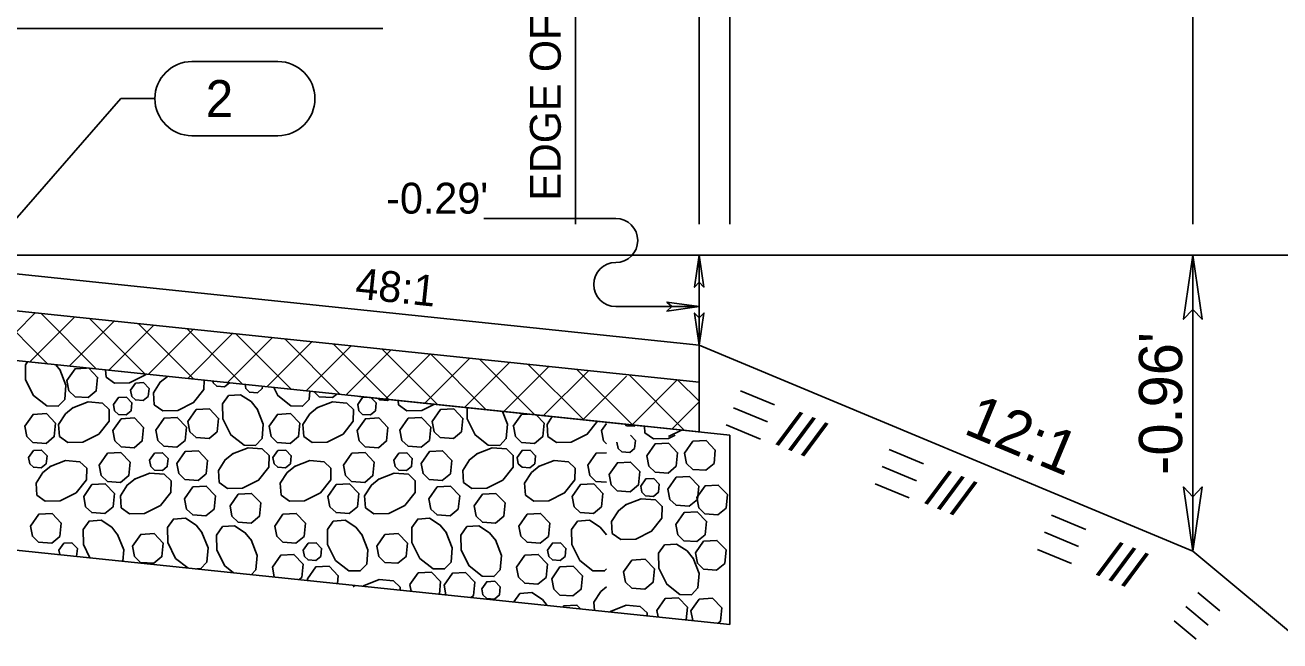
# Model space of a CAD drawing. Extents: x 6561 to 6787, y 19927 to 20919.
# Drawn here: x 6704.14 to 6724.47, y 20747.4 to 20757.37 of the extents above; entities that cross this region are included whole.
import ezdxf

# ---------------------------------------------------------------- set-up
doc = ezdxf.new("R2010")
doc.units = 0
for name, color, linetype in [('Level 1', 7, 'Continuous'), ('Level 3', 7, 'Continuous'), ('Level 5', 7, 'Continuous'), ('Level 7', 7, 'Continuous'), ('Level 8', 7, 'Continuous')]:
    doc.layers.add(name, color=color, linetype=linetype)

msp = doc.modelspace()

# ---------------------------------------------------------------- linework, layer by layer
at = {"layer": 'Level 1'}
for p, q in [((6723.057, 20767.65), (6723.057, 20754.15)), ((6713.057, 20764.65), (6713.057, 20754.15)), ((6715.057, 20764.65), (6715.057, 20754.15)), ((6715.557, 20762.65), (6715.557, 20754.15)), ((6713.708, 20754.242), (6711.572, 20754.242)), ((6779.047, 20753.65), (6628.473, 20753.65)), ((6715.057, 20753.65), (6715.057, 20752.192)), ((6723.057, 20748.858), (6723.057, 20753.65)), ((6713.708, 20752.817), (6715.057, 20752.817))]:
    msp.add_line(p, q, dxfattribs=at)
for points in [[(6715.057, 20753.65), (6714.985, 20753.13), (6715.059, 20753.211), (6715.135, 20753.131)], [(6723.057, 20753.65), (6722.907, 20752.611), (6723.057, 20752.771), (6723.207, 20752.611)], [(6715.057, 20752.817), (6714.537, 20752.889), (6714.618, 20752.815), (6714.538, 20752.739)], [(6715.057, 20752.192), (6714.985, 20752.711), (6715.059, 20752.631), (6715.135, 20752.711)], [(6723.057, 20748.858), (6723.207, 20749.897), (6723.057, 20749.737), (6722.907, 20749.897)]]:
    msp.add_lwpolyline(points, close=True, dxfattribs=at)
for centre, start, end in [((6713.708, 20753.886), 270, 90), ((6713.708, 20753.173), 90, 270)]:
    msp.add_arc(centre, 0.356, start, end, dxfattribs=at)
at = {"layer": 'Level 3'}
for p, q in [((6715.057, 20751.592), (6701.057, 20753.05)), ((6704.299, 20752.712), (6703.571, 20751.984)), ((6704.506, 20751.886), (6703.608, 20752.784)), ((6704.94, 20752.645), (6704.211, 20751.917)), ((6705.295, 20751.804), (6704.398, 20752.702)), ((6705.58, 20752.579), (6704.852, 20751.85)), ((6706.085, 20751.722), (6705.187, 20752.62)), ((6706.221, 20752.512), (6705.492, 20751.784)), ((6706.874, 20751.64), (6705.976, 20752.537)), ((6706.861, 20752.445), (6706.133, 20751.717)), ((6707.663, 20751.557), (6706.766, 20752.455)), ((6707.501, 20752.379), (6706.773, 20751.65)), ((6708.142, 20752.312), (6707.413, 20751.583)), ((6708.453, 20751.475), (6707.555, 20752.373)), ((6701.057, 20752.246), (6715.057, 20750.787)), ((6708.782, 20752.245), (6708.054, 20751.517)), ((6709.242, 20751.393), (6708.344, 20752.291)), ((6709.423, 20752.178), (6708.694, 20751.45)), ((6710.031, 20751.311), (6709.134, 20752.209)), ((6710.063, 20752.112), (6709.335, 20751.383)), ((6710.821, 20751.229), (6709.923, 20752.126)), ((6710.703, 20752.045), (6709.975, 20751.317)), ((6711.344, 20751.978), (6710.615, 20751.25)), ((6711.61, 20751.146), (6710.712, 20752.044)), ((6711.984, 20751.912), (6711.256, 20751.183)), ((6712.399, 20751.064), (6711.501, 20751.962)), ((6712.625, 20751.845), (6711.896, 20751.116)), ((6713.189, 20750.982), (6712.291, 20751.88)), ((6713.265, 20751.778), (6712.537, 20751.05)), ((6713.966, 20750.912), (6713.08, 20751.797)), ((6714.821, 20750.812), (6713.923, 20751.71)), ((6713.881, 20751.687), (6713.177, 20750.983)), ((6714.703, 20751.628), (6713.975, 20750.9)), ((6715.057, 20751.283), (6714.712, 20751.627)), ((6715.057, 20750.787), (6715.057, 20751.592)), ((6715.057, 20751.275), (6714.615, 20750.833))]:
    msp.add_line(p, q, dxfattribs=at)
at = {"layer": 'Level 5'}
for p, q in [((6701.057, 20752.246), (6713.557, 20750.944)), ((6709.557, 20751.36), (6714.16, 20750.881)), ((6714.174, 20750.879), (6715.557, 20750.735)), ((6715.557, 20750.735), (6715.557, 20747.669)), ((6715.557, 20747.669), (6701.057, 20749.179))]:
    msp.add_line(p, q, dxfattribs=at)
for points in [[(6704.701, 20751.796), (6704.8, 20751.544), (6704.78, 20751.313), (6704.676, 20751.203), (6704.489, 20751.207), (6704.275, 20751.374), (6704.147, 20751.631), (6704.142, 20751.874), (6704.176, 20751.921)], [(6704.638, 20751.873), (6704.707, 20751.786)], [(6704.815, 20751.619), (6704.949, 20751.81), (6705.135, 20751.821)], [(6705.169, 20751.817), (6705.313, 20751.668), (6705.292, 20751.451), (6705.159, 20751.341), (6704.947, 20751.356), (6704.847, 20751.453), (6704.815, 20751.619)], [(6706.096, 20751.721), (6706.088, 20751.711), (6705.83, 20751.582), (6705.588, 20751.578), (6705.451, 20751.675), (6705.443, 20751.789)], [(6705.847, 20751.462), (6705.927, 20751.577), (6706.056, 20751.584), (6706.146, 20751.491), (6706.133, 20751.361), (6706.053, 20751.295), (6705.926, 20751.304), (6705.866, 20751.362), (6705.847, 20751.462)], [(6707.038, 20751.623), (6707.035, 20751.474), (6706.868, 20751.261), (6706.611, 20751.133), (6706.368, 20751.128), (6706.231, 20751.225), (6706.218, 20751.419), (6706.329, 20751.592), (6706.445, 20751.684)], [(6707.448, 20751.58), (6707.371, 20751.516), (6707.244, 20751.525), (6707.184, 20751.583), (6707.179, 20751.608)], [(6707.984, 20751.524), (6707.98, 20751.487), (6707.901, 20751.421), (6707.773, 20751.43), (6707.714, 20751.488), (6707.701, 20751.554)], [(6708.749, 20751.444), (6708.738, 20751.313), (6708.633, 20751.203), (6708.446, 20751.207), (6708.233, 20751.374), (6708.167, 20751.505)], [(6705.569, 20751.229), (6705.65, 20751.343), (6705.779, 20751.351), (6705.868, 20751.258), (6705.855, 20751.128), (6705.776, 20751.062), (6705.649, 20751.071), (6705.589, 20751.129), (6705.569, 20751.229)], [(6707.897, 20751.161), (6707.997, 20750.91), (6707.977, 20750.679), (6707.873, 20750.569), (6707.685, 20750.572), (6707.472, 20750.739), (6707.343, 20750.997), (6707.339, 20751.239), (6707.436, 20751.376), (6707.629, 20751.389), (6707.802, 20751.278), (6707.904, 20751.151)], [(6709.187, 20751.399), (6709.116, 20751.341), (6708.905, 20751.356), (6708.821, 20751.437)], [(6709.527, 20751.229), (6709.607, 20751.343), (6709.679, 20751.347)], [(6709.746, 20751.34), (6709.826, 20751.258), (6709.813, 20751.128), (6709.733, 20751.062), (6709.606, 20751.071), (6709.546, 20751.129), (6709.527, 20751.229)], [(6710.03, 20751.311), (6710.011, 20751.295), (6709.883, 20751.304), (6709.858, 20751.329)], [(6710.771, 20751.234), (6710.568, 20751.133), (6710.325, 20751.128), (6710.189, 20751.225), (6710.184, 20751.295)], [(6704.909, 20751.174), (6705.16, 20751.274), (6705.391, 20751.254), (6705.501, 20751.149), (6705.498, 20750.962), (6705.331, 20750.749), (6705.074, 20750.62), (6704.831, 20750.616), (6704.694, 20750.713), (6704.681, 20750.906), (6704.792, 20751.079), (6704.919, 20751.181)], [(6706.775, 20750.956), (6706.91, 20751.148), (6707.125, 20751.16), (6707.274, 20751.005), (6707.252, 20750.788), (6707.12, 20750.678), (6706.908, 20750.694), (6706.808, 20750.79), (6706.776, 20750.956)], [(6708.866, 20751.174), (6709.118, 20751.274), (6709.349, 20751.254), (6709.459, 20751.149), (6709.455, 20750.962), (6709.289, 20750.749), (6709.031, 20750.62), (6708.788, 20750.616), (6708.652, 20750.713), (6708.639, 20750.906), (6708.75, 20751.079), (6708.877, 20751.181)], [(6710.733, 20750.956), (6710.867, 20751.148), (6711.082, 20751.16), (6711.231, 20751.005), (6711.21, 20750.788), (6711.077, 20750.678), (6710.865, 20750.694), (6710.765, 20750.79), (6710.733, 20750.956)], [(6711.871, 20751.119), (6711.954, 20750.91), (6711.934, 20750.679), (6711.83, 20750.569), (6711.643, 20750.572), (6711.429, 20750.739), (6711.301, 20750.997), (6711.298, 20751.179)], [(6704.134, 20750.879), (6704.268, 20751.071), (6704.483, 20751.083), (6704.632, 20750.928), (6704.61, 20750.711), (6704.478, 20750.601), (6704.266, 20750.616), (6704.166, 20750.713), (6704.134, 20750.879)], [(6705.56, 20750.808), (6705.695, 20751), (6705.909, 20751.012), (6706.059, 20750.857), (6706.037, 20750.64), (6705.904, 20750.53), (6705.693, 20750.545), (6705.593, 20750.642), (6705.56, 20750.808)], [(6706.254, 20750.816), (6706.389, 20751.007), (6706.603, 20751.02), (6706.752, 20750.865), (6706.731, 20750.648), (6706.598, 20750.538), (6706.386, 20750.553), (6706.287, 20750.65), (6706.254, 20750.816)], [(6708.091, 20750.879), (6708.225, 20751.071), (6708.44, 20751.083), (6708.589, 20750.928), (6708.568, 20750.711), (6708.435, 20750.601), (6708.223, 20750.616), (6708.123, 20750.713), (6708.091, 20750.879)], [(6709.518, 20750.808), (6709.652, 20751), (6709.867, 20751.012), (6710.016, 20750.857), (6709.995, 20750.64), (6709.862, 20750.53), (6709.65, 20750.545), (6709.55, 20750.642), (6709.518, 20750.808)], [(6710.211, 20750.816), (6710.346, 20751.007), (6710.561, 20751.02), (6710.71, 20750.865), (6710.688, 20750.648), (6710.556, 20750.538), (6710.344, 20750.553), (6710.244, 20750.65), (6710.212, 20750.816)], [(6712.048, 20750.879), (6712.183, 20751.071), (6712.283, 20751.076)], [(6712.417, 20751.062), (6712.547, 20750.928), (6712.525, 20750.711), (6712.393, 20750.601), (6712.181, 20750.616), (6712.081, 20750.713), (6712.049, 20750.879)], [(6713.41, 20750.959), (6713.246, 20750.749), (6712.988, 20750.62), (6712.746, 20750.616), (6712.609, 20750.713), (6712.596, 20750.906), (6712.679, 20751.035)], [(6713.475, 20750.808), (6713.557, 20750.925)], [(6714.03, 20750.894), (6714.011, 20750.878), (6713.883, 20750.887), (6713.858, 20750.912)], [(6713.557, 20750.594), (6713.508, 20750.642), (6713.475, 20750.808)], [(6713.947, 20750.732), (6714.026, 20750.649), (6714.013, 20750.519), (6713.934, 20750.453), (6713.807, 20750.462), (6713.747, 20750.52), (6713.727, 20750.62)], [(6714.669, 20750.732), (6714.561, 20750.678), (6714.318, 20750.674), (6714.181, 20750.771), (6714.174, 20750.879)], [(6714.771, 20750.817), (6714.564, 20750.714)], [(6704.195, 20750.371), (6704.275, 20750.486), (6704.404, 20750.493), (6704.494, 20750.4), (6704.481, 20750.27), (6704.401, 20750.204), (6704.274, 20750.213), (6704.214, 20750.271), (6704.195, 20750.371)], [(6706.596, 20750.277), (6706.731, 20750.469), (6706.945, 20750.481), (6707.095, 20750.326), (6707.073, 20750.109), (6706.94, 20749.999), (6706.728, 20750.014), (6706.629, 20750.111), (6706.596, 20750.277)], [(6707.499, 20750.43), (6707.75, 20750.53), (6707.981, 20750.51), (6708.091, 20750.406), (6708.087, 20750.218), (6707.921, 20750.005), (6707.663, 20749.876), (6707.42, 20749.872), (6707.284, 20749.969), (6707.271, 20750.162), (6707.382, 20750.335), (6707.509, 20750.437)], [(6708.152, 20750.371), (6708.233, 20750.486), (6708.362, 20750.493), (6708.451, 20750.4), (6708.438, 20750.27), (6708.359, 20750.204), (6708.232, 20750.213), (6708.172, 20750.271), (6708.152, 20750.371)], [(6710.554, 20750.277), (6710.688, 20750.469), (6710.903, 20750.481), (6711.052, 20750.326), (6711.03, 20750.109), (6710.898, 20749.999), (6710.686, 20750.014), (6710.586, 20750.111), (6710.554, 20750.277)], [(6711.456, 20750.43), (6711.707, 20750.53), (6711.939, 20750.51), (6712.048, 20750.406), (6712.045, 20750.218), (6711.878, 20750.005), (6711.621, 20749.876), (6711.378, 20749.872), (6711.241, 20749.969), (6711.228, 20750.162), (6711.339, 20750.335), (6711.466, 20750.437)], [(6712.11, 20750.371), (6712.19, 20750.486), (6712.319, 20750.493), (6712.409, 20750.4), (6712.396, 20750.27), (6712.316, 20750.204), (6712.189, 20750.213), (6712.129, 20750.271), (6712.11, 20750.371)], [(6714.211, 20750.4), (6714.346, 20750.591), (6714.561, 20750.603), (6714.71, 20750.448), (6714.688, 20750.232), (6714.556, 20750.121), (6714.344, 20750.137), (6714.244, 20750.233), (6714.212, 20750.4)], [(6714.823, 20750.443), (6714.958, 20750.635), (6715.172, 20750.647), (6715.321, 20750.492), (6715.3, 20750.275), (6715.167, 20750.165), (6714.955, 20750.18), (6714.856, 20750.277), (6714.823, 20750.443)], [(6704.543, 20750.224), (6704.795, 20750.323), (6705.026, 20750.304), (6705.136, 20750.199), (6705.132, 20750.012), (6704.965, 20749.799), (6704.708, 20749.67), (6704.465, 20749.666), (6704.328, 20749.763), (6704.316, 20749.956), (6704.426, 20750.129), (6704.553, 20750.23)], [(6705.34, 20750.248), (6705.474, 20750.44), (6705.689, 20750.452), (6705.838, 20750.297), (6705.817, 20750.08), (6705.684, 20749.97), (6705.472, 20749.985), (6705.372, 20750.082), (6705.34, 20750.248)], [(6706.156, 20750.327), (6706.236, 20750.442), (6706.365, 20750.449), (6706.455, 20750.356), (6706.442, 20750.226), (6706.362, 20750.16), (6706.235, 20750.169), (6706.175, 20750.227), (6706.156, 20750.327)], [(6708.501, 20750.224), (6708.752, 20750.323), (6708.983, 20750.304), (6709.093, 20750.199), (6709.09, 20750.012), (6708.923, 20749.799), (6708.665, 20749.67), (6708.423, 20749.666), (6708.286, 20749.763), (6708.273, 20749.956), (6708.384, 20750.129), (6708.511, 20750.23)], [(6709.297, 20750.248), (6709.432, 20750.44), (6709.646, 20750.452), (6709.796, 20750.297), (6709.774, 20750.08), (6709.641, 20749.97), (6709.429, 20749.985), (6709.33, 20750.082), (6709.297, 20750.248)], [(6710.113, 20750.327), (6710.194, 20750.442), (6710.323, 20750.449), (6710.412, 20750.356), (6710.399, 20750.226), (6710.32, 20750.16), (6710.192, 20750.169), (6710.133, 20750.227), (6710.113, 20750.327)], [(6712.458, 20750.224), (6712.71, 20750.323), (6712.941, 20750.304), (6713.05, 20750.199), (6713.047, 20750.012), (6712.88, 20749.799), (6712.623, 20749.67), (6712.38, 20749.666), (6712.243, 20749.763), (6712.23, 20749.956), (6712.341, 20750.129), (6712.468, 20750.23)], [(6713.255, 20750.248), (6713.389, 20750.44), (6713.557, 20750.449)], [(6713.6, 20750.095), (6713.734, 20750.287), (6713.949, 20750.299), (6714.098, 20750.144), (6714.076, 20749.927), (6713.944, 20749.817), (6713.732, 20749.832), (6713.632, 20749.929), (6713.6, 20750.095)], [(6705.91, 20750.02), (6706.161, 20750.12), (6706.392, 20750.1), (6706.502, 20749.996), (6706.499, 20749.808), (6706.332, 20749.595), (6706.074, 20749.466), (6705.832, 20749.462), (6705.695, 20749.559), (6705.682, 20749.753), (6705.793, 20749.926), (6705.92, 20750.027)], [(6709.867, 20750.02), (6710.119, 20750.12), (6710.35, 20750.1), (6710.46, 20749.996), (6710.456, 20749.808), (6710.289, 20749.595), (6710.032, 20749.466), (6709.789, 20749.462), (6709.652, 20749.559), (6709.639, 20749.753), (6709.75, 20749.926), (6709.877, 20750.027)], [(6713.557, 20749.973), (6713.387, 20749.985), (6713.287, 20750.082), (6713.255, 20750.248)], [(6705.087, 20749.742), (6705.221, 20749.934), (6705.436, 20749.946), (6705.585, 20749.791), (6705.564, 20749.574), (6705.431, 20749.464), (6705.219, 20749.479), (6705.119, 20749.576), (6705.087, 20749.742)], [(6706.723, 20749.705), (6706.857, 20749.896), (6707.072, 20749.908), (6707.221, 20749.754), (6707.2, 20749.537), (6707.067, 20749.426), (6706.855, 20749.442), (6706.755, 20749.538), (6706.723, 20749.705)], [(6709.044, 20749.742), (6709.179, 20749.934), (6709.393, 20749.946), (6709.543, 20749.791), (6709.521, 20749.574), (6709.388, 20749.464), (6709.176, 20749.479), (6709.077, 20749.576), (6709.044, 20749.742)], [(6710.68, 20749.705), (6710.815, 20749.896), (6711.029, 20749.908), (6711.179, 20749.754), (6711.157, 20749.537), (6711.024, 20749.426), (6710.812, 20749.442), (6710.713, 20749.538), (6710.68, 20749.705)], [(6713.002, 20749.742), (6713.136, 20749.934), (6713.351, 20749.946), (6713.5, 20749.791), (6713.478, 20749.574), (6713.346, 20749.464), (6713.134, 20749.479), (6713.034, 20749.576), (6713.002, 20749.742)], [(6714.113, 20749.91), (6714.194, 20750.025), (6714.323, 20750.032), (6714.412, 20749.94), (6714.399, 20749.809), (6714.32, 20749.743), (6714.192, 20749.752), (6714.133, 20749.81), (6714.113, 20749.91)], [(6714.554, 20749.861), (6714.688, 20750.052), (6714.903, 20750.064), (6715.052, 20749.909), (6715.03, 20749.693), (6714.898, 20749.582), (6714.686, 20749.598), (6714.586, 20749.694), (6714.554, 20749.861)], [(6715.02, 20749.722), (6715.154, 20749.913), (6715.369, 20749.925), (6715.518, 20749.771), (6715.496, 20749.554), (6715.364, 20749.444), (6715.152, 20749.459), (6715.052, 20749.556), (6715.02, 20749.722)], [(6707.458, 20749.588), (6707.592, 20749.779), (6707.807, 20749.791), (6707.956, 20749.636), (6707.935, 20749.42), (6707.802, 20749.309), (6707.59, 20749.325), (6707.49, 20749.421), (6707.458, 20749.588)], [(6711.415, 20749.588), (6711.55, 20749.779), (6711.764, 20749.791), (6711.914, 20749.636), (6711.892, 20749.42), (6711.759, 20749.309), (6711.547, 20749.325), (6711.448, 20749.421), (6711.415, 20749.588)], [(6713.867, 20749.604), (6714.119, 20749.703), (6714.35, 20749.684), (6714.46, 20749.579), (6714.456, 20749.392), (6714.289, 20749.179), (6714.032, 20749.05), (6713.789, 20749.046), (6713.652, 20749.143), (6713.639, 20749.336), (6713.75, 20749.509), (6713.877, 20749.61)], [(6704.225, 20749.262), (6704.359, 20749.454), (6704.574, 20749.466), (6704.723, 20749.311), (6704.701, 20749.094), (6704.569, 20748.984), (6704.357, 20748.999), (6704.257, 20749.096), (6704.225, 20749.262)], [(6708.182, 20749.262), (6708.316, 20749.454), (6708.531, 20749.466), (6708.68, 20749.311), (6708.659, 20749.094), (6708.526, 20748.984), (6708.314, 20748.999), (6708.215, 20749.096), (6708.182, 20749.262)], [(6712.139, 20749.262), (6712.274, 20749.454), (6712.489, 20749.466), (6712.638, 20749.311), (6712.616, 20749.094), (6712.484, 20748.984), (6712.272, 20748.999), (6712.172, 20749.096), (6712.14, 20749.262)], [(6714.68, 20749.288), (6714.815, 20749.479), (6715.029, 20749.492), (6715.179, 20749.337), (6715.157, 20749.12), (6715.024, 20749.01), (6714.812, 20749.025), (6714.713, 20749.122), (6714.68, 20749.288)], [(6705.189, 20748.749), (6705.082, 20748.963), (6705.078, 20749.205), (6705.175, 20749.342), (6705.368, 20749.355), (6705.541, 20749.244), (6705.643, 20749.117)], [(6706.774, 20748.584), (6706.577, 20748.738), (6706.449, 20748.995), (6706.444, 20749.238), (6706.541, 20749.375), (6706.735, 20749.388), (6706.908, 20749.277), (6707.009, 20749.15)], [(6707.514, 20748.506), (6707.375, 20748.616), (6707.246, 20748.873), (6707.241, 20749.116), (6707.339, 20749.253), (6707.532, 20749.266), (6707.705, 20749.155), (6707.806, 20749.028)], [(6709.593, 20749.127), (6709.693, 20748.876), (6709.673, 20748.645), (6709.569, 20748.535), (6709.381, 20748.538), (6709.168, 20748.705), (6709.04, 20748.963), (6709.035, 20749.205), (6709.132, 20749.342), (6709.326, 20749.355), (6709.499, 20749.244), (6709.6, 20749.117)], [(6710.96, 20749.16), (6711.06, 20748.908), (6711.04, 20748.677), (6710.935, 20748.567), (6710.748, 20748.571), (6710.535, 20748.738), (6710.406, 20748.995), (6710.402, 20749.238), (6710.499, 20749.375), (6710.692, 20749.388), (6710.865, 20749.277), (6710.966, 20749.15)], [(6711.757, 20749.038), (6711.857, 20748.786), (6711.837, 20748.555), (6711.733, 20748.445), (6711.545, 20748.449), (6711.332, 20748.616), (6711.203, 20748.873), (6711.199, 20749.116), (6711.296, 20749.253), (6711.489, 20749.266), (6711.662, 20749.155), (6711.764, 20749.028)], [(6713.557, 20748.567), (6713.526, 20748.535), (6713.339, 20748.538), (6713.126, 20748.705), (6712.997, 20748.963), (6712.993, 20749.205), (6713.09, 20749.342), (6713.283, 20749.355), (6713.456, 20749.244), (6713.557, 20749.118)], [(6705.636, 20749.127), (6705.736, 20748.876), (6705.72, 20748.693)], [(6705.878, 20748.937), (6706.012, 20749.128), (6706.227, 20749.141), (6706.376, 20748.986), (6706.354, 20748.769), (6706.222, 20748.659), (6706.01, 20748.674), (6705.91, 20748.771), (6705.878, 20748.937)], [(6707.003, 20749.16), (6707.102, 20748.908), (6707.082, 20748.677), (6706.978, 20748.567), (6706.918, 20748.569)], [(6709.835, 20748.937), (6709.969, 20749.128), (6710.184, 20749.141), (6710.333, 20748.986), (6710.312, 20748.769), (6710.179, 20748.659), (6709.967, 20748.674), (6709.867, 20748.771), (6709.835, 20748.937)], [(6704.687, 20748.87), (6704.767, 20748.985), (6704.896, 20748.993), (6704.986, 20748.9), (6704.973, 20748.771)], [(6704.7, 20748.8), (6704.687, 20748.87)], [(6707.8, 20749.038), (6707.899, 20748.786), (6707.879, 20748.555), (6707.804, 20748.476)], [(6708.644, 20748.87), (6708.725, 20748.985), (6708.854, 20748.993), (6708.943, 20748.9), (6708.93, 20748.77), (6708.851, 20748.703), (6708.723, 20748.713), (6708.663, 20748.771), (6708.644, 20748.87)], [(6712.601, 20748.87), (6712.682, 20748.985), (6712.811, 20748.993), (6712.9, 20748.9), (6712.888, 20748.77), (6712.808, 20748.703), (6712.681, 20748.713), (6712.621, 20748.771), (6712.602, 20748.87)], [(6714.96, 20748.743), (6715.06, 20748.492), (6715.04, 20748.261), (6714.935, 20748.151), (6714.748, 20748.154), (6714.535, 20748.321), (6714.406, 20748.579), (6714.402, 20748.821), (6714.499, 20748.958), (6714.692, 20748.971), (6714.865, 20748.86), (6714.966, 20748.733)], [(6714.998, 20748.826), (6715.132, 20749.017), (6715.347, 20749.029), (6715.496, 20748.875), (6715.475, 20748.658), (6715.342, 20748.547), (6715.13, 20748.563), (6715.03, 20748.66), (6714.998, 20748.826)], [(6708.144, 20748.598), (6708.279, 20748.789), (6708.494, 20748.802), (6708.643, 20748.647), (6708.621, 20748.43), (6708.579, 20748.395)], [(6712.102, 20748.598), (6712.236, 20748.789), (6712.451, 20748.802), (6712.6, 20748.647), (6712.579, 20748.43), (6712.446, 20748.32), (6712.234, 20748.335), (6712.134, 20748.432), (6712.102, 20748.598)], [(6713.835, 20748.52), (6713.969, 20748.712), (6714.184, 20748.724), (6714.333, 20748.569), (6714.312, 20748.352), (6714.179, 20748.242), (6713.967, 20748.257), (6713.867, 20748.354), (6713.835, 20748.52)], [(6708.176, 20748.438), (6708.145, 20748.598)], [(6708.713, 20748.408), (6708.847, 20748.6), (6709.062, 20748.612), (6709.211, 20748.457), (6709.198, 20748.331)], [(6710.373, 20748.314), (6710.508, 20748.505), (6710.722, 20748.517), (6710.871, 20748.362), (6710.851, 20748.159)], [(6710.926, 20748.305), (6711.061, 20748.497), (6711.275, 20748.509), (6711.425, 20748.354), (6711.403, 20748.137), (6711.365, 20748.105)], [(6712.67, 20748.408), (6712.804, 20748.6), (6713.019, 20748.612), (6713.168, 20748.457), (6713.147, 20748.24), (6713.014, 20748.13), (6712.802, 20748.145), (6712.702, 20748.242), (6712.67, 20748.408)], [(6708.718, 20748.381), (6708.713, 20748.408)], [(6709.455, 20748.277), (6709.473, 20748.292)], [(6709.615, 20748.288), (6709.633, 20748.302)], [(6709.623, 20748.296), (6709.875, 20748.396), (6710.106, 20748.376), (6710.216, 20748.271), (6710.215, 20748.225)], [(6710.394, 20748.206), (6710.373, 20748.313)], [(6710.957, 20748.148), (6710.926, 20748.305)], [(6711.538, 20748.246), (6711.619, 20748.361), (6711.747, 20748.368), (6711.837, 20748.276), (6711.824, 20748.146), (6711.745, 20748.079), (6711.617, 20748.089), (6711.557, 20748.147), (6711.538, 20748.246)], [(6713.362, 20747.897), (6713.353, 20748.028), (6713.464, 20748.201), (6713.557, 20748.276)], [(6712.057, 20748.033), (6712.057, 20748.034), (6712.154, 20748.171), (6712.348, 20748.184), (6712.521, 20748.073), (6712.597, 20747.977)], [(6714.373, 20747.897), (6714.508, 20748.088), (6714.722, 20748.1), (6714.871, 20747.946), (6714.851, 20747.742)], [(6714.926, 20747.889), (6715.061, 20748.08), (6715.275, 20748.092), (6715.425, 20747.938), (6715.403, 20747.721), (6715.365, 20747.689)], [(6712.85, 20747.951), (6712.864, 20747.97), (6713.079, 20747.983), (6713.139, 20747.921)], [(6713.615, 20747.871), (6713.633, 20747.886)], [(6713.623, 20747.879), (6713.875, 20747.979), (6714.106, 20747.959), (6714.216, 20747.855), (6714.215, 20747.808)], [(6714.394, 20747.79), (6714.373, 20747.897)], [(6714.957, 20747.731), (6714.926, 20747.889)]]:
    msp.add_lwpolyline(points, dxfattribs=at)
at = {"layer": 'Level 7'}
for p, q in [((6715.057, 20752.192), (6723.057, 20748.858)), ((6723.057, 20748.858), (6733.557, 20740.108))]:
    msp.add_line(p, q, dxfattribs=at)
for points in [[(6715.728, 20751.454), (6716.282, 20751.223)], [(6715.613, 20751.177), (6716.167, 20750.947)], [(6715.498, 20750.901), (6716.052, 20750.67)], [(6718.14, 20750.501), (6718.694, 20750.271)], [(6718.025, 20750.225), (6718.579, 20749.994)], [(6717.91, 20749.948), (6718.464, 20749.717)], [(6720.769, 20749.437), (6721.323, 20749.207)], [(6720.654, 20749.161), (6721.208, 20748.93)], [(6720.539, 20748.884), (6721.093, 20748.654)], [(6723.139, 20748.187), (6723.497, 20747.888)], [(6722.947, 20747.957), (6723.305, 20747.658)], [(6722.755, 20747.727), (6723.113, 20747.428)]]:
    msp.add_lwpolyline(points, dxfattribs=at)
at = {"layer": 'Level 8'}
for p, q in [((6703.419, 20757.316), (6709.936, 20757.316)), ((6708.234, 20756.783), (6706.841, 20756.783)), ((6705.69, 20756.183), (6702.152, 20752.132)), ((6705.69, 20756.183), (6706.241, 20756.183)), ((6706.841, 20755.583), (6708.234, 20755.583)), ((6701.057, 20753.65), (6715.057, 20752.192)), ((6715.057, 20751.592), (6701.057, 20753.05)), ((6715.057, 20752.192), (6715.057, 20751.592))]:
    msp.add_line(p, q, dxfattribs=at)
for centre, start, end in [((6706.841, 20756.183), 90, 270), ((6708.234, 20756.183), 270, 90)]:
    msp.add_arc(centre, 0.6, start, end, dxfattribs=at)

# ---------------------------------------------------------------- texts
at = {"layer": 'Level 1'}
for s, height, rotation, p in [('EDGE OF TRAVELWAY', 0.5, 90, (6712.817, 20754.532)), ('48:1', 0.5, 354.0531, (6709.474, 20752.949)), ("-0.96'", 0.7, 90, (6722.885, 20750.091)), ('12:1', 0.7, 337.3801, (6719.322, 20750.768))]:
    msp.add_text(s, height=height, rotation=rotation, dxfattribs=at).set_placement(p)
msp.add_text("-0.29'", height=0.5, dxfattribs=at).set_placement((6709.989, 20754.321))
at = {"layer": 'Level 7'}
for p in [(6716.297, 20750.593), (6718.709, 20749.64), (6721.488, 20748.482)]:
    msp.add_text('///', height=0.6, rotation=337.3802, dxfattribs=at).set_placement(p)
at = {"layer": 'Level 8'}
msp.add_text(' 2', height=0.6, dxfattribs=at).set_placement((6706.841, 20755.883))

doc.saveas('drawing.dxf')
